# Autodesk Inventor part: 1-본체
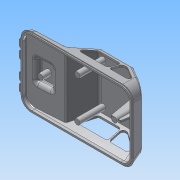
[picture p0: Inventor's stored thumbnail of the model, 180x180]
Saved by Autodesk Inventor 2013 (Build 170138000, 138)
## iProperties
Created: 2015-05
Part Number: 1-본체
Material: ABS 플라스틱
Document SubType Name: Modeling
Designer: Administrator
Density: 1.06 g/cm^3
Mass: 30.7394 g
Surface Area: 295.801 cm^2
Volume: 28.9994 cm^3
Author: Administrator
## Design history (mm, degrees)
sketch "스케치1"
  geometry: L1 (1, -1)-(121, -1); L2 (122, 0)-(118.782, 12.011); L3 (0, 0)-(1.34, 5); L4 (1.34, 5)-(42, 7.131); L5 (56.29, 30)-(92, 30); L6 (92, 30)-(118.782, 12.011); L7 (0, 0)-(1, 0); L8 (1, 0)-(1, -1); L9 (121, -1)-(121, 0); L10 (121, 0)-(122, 0); L11 (42, 7.131)-(56.29, 30); L12 (122, 0)-(122, 10); L13 (118.782, 12.011)-(122, 10); 1 further point
  constraints: 26 end point, 4 perpendicular, 3 parallel, 1 coincident, 1 horizontal
  dimensions: "d1" = 105 deg angle of L1 L2; "d2" = 31 distance between parallel lines of L1 L5; "d9" = 42 horizontal distance of L4.end L3.start; "d10" = 1 distance of L3.start L7.end; "d11" = 1 distance of L7.end L1.start; "d12" = 6 distance from line of L3.end L1; "d14" = 105 deg angle of L3 L1; "d15" = 1 distance of L9.end L2.start; "d16" = 1 distance of L1.end L9.end; "d17" = 30 horizontal distance of L5.end L2.start; "d18" = 122 distance of L2.start L3.start; "d57" = 125 deg angle of L11 L4; "d58" = 3 deg angle of L1 L4; "d137" = 20 distance from line of L12.end L5
extrude "돌출1" new body sketch "스케치1" stored distance "d19" = 76; taper "d20" = 0 deg
node "작업 평면2"
node "작업 평면3"
node "작업 평면4"
node "작업 평면5"
sketch "스케치7"
  geometry: L1 (1, -38)-(0, -38) reference; L2 (0, -38)-(-5, -38) reference; L3 (-5, -38)-(-7.131, -38) reference; L4 (-7.131, -38)-(-7.131, 38) reference; L5 (-30, 38)-(-7.131, 38) reference; L6 (-30, -38)-(-30, 38) reference; L7 (-7.131, -38)-(-30, -38) reference; L8 (1, -38)-(1, 38) reference; L9 (1, -37)-(0, -37); L10 (0, -37)-(0, -38); L11 (0, -38)-(-30, -29.962); L12 (0, 0)-(12, 0); L13 (0, 38)-(-30, 29.962); L14 (0, 37)-(0, 38); L15 (1, 37)-(0, 37); L16 (0, -38)-(1, -38); L17 (1, -37)-(1, -38); L18 (0, -38)-(-30, -38); L19 (-30, -29.962)-(-30, -38); L20 (1, 37)-(1, 38); L21 (1, 38)-(0, 38); L22 (0, 38)-(-30, 38); L23 (-30, 38)-(-30, 29.962)
  constraints: 30 end point, 5 perpendicular, 4 symmetric about line, 3 point on line, 1 collinear
  dimensions: "d84" = 1 distance of L9.end L10.end; "d86" = 1 distance of L9.start L9.end; "d87" = 105 deg angle of L8 L11; "d88" = 105 deg angle of L8 L13
extrude "돌출5" cut sketch "스케치7" stored distance "d89" = 5; taper "d90" = 0 deg
sketch "스케치8"
  geometry: L1 (9.4, 23.66)-(29.4, 23.66); L2 (29.4, 23.66)-(29.4, 49.66); L3 (29.4, 49.66)-(9.4, 49.66); L4 (9.4, 49.66)-(9.4, 23.66); L5 (-1.6, 74.66)-(-1.6, -1.34) reference; 2 further points
  constraints: 8 end point, 2 parallel, 1 horizontal, 1 horizontal alignment, 1 midpoint, 1 perpendicular
  dimensions: "d91" = 26 distance of L1.end L2.end; "d93" = 20 distance of L2.end L3.end; "d94" = 11 distance between parallel lines of L4 L5
extrude "돌출6" join sketch "스케치8" distance "d95" = 5; taper "d96" = -20 deg
fillet "모깎기5" dims "d97" = 3
fillet "모깎기6" dims "d98" = 3
fillet "모깎기7" dims "d99" = 12
feature "쉘1" dims "d42" = 2
node "작업 평면6"
sketch "스케치11"
  geometry: L1 (42, 7.131)-(56.29, 30) reference; L2 (56.29, 30)-(92, 30) reference; L3 (92, 30)-(104.647, 21.505) reference; L4 (104.647, 21.505)-(118.782, 12.011) reference; L5 (49.689, 10)-(59.062, 25); L6 (59.062, 25)-(90.477, 25); L7 (11.591, 0)-(110.409, 0) reference; L8 (109, -1)-(13, -1) reference; L9 (112.808, 10)-(49.689, 10); L10 (83.689, 10)-(83.689, 25); L11 (84.808, 10)-(84.808, 25); L12 (112.808, 10)-(90.477, 25); 1 further point
  constraints: 12 end point, 4 point on line, 3 parallel, 2 perpendicular
  dimensions: "d126" = 5 distance between parallel lines of L1 L5; "d128" = 5 distance between parallel lines of L2 L6; "d129" = 15 distance between parallel lines of L9 L6; "d135" = 34 distance from line of L10 L5.start; "d136" = 28 distance from line of L11 L9.start; "d138" = 5 distance between parallel lines of L3 L12
extrude "돌출8" cut sketch "스케치11" stored distance "d139" = 5; taper "d140" = 0 deg
node "작업 평면7"
sketch "스케치12"
  geometry: L1 (0, 0)-(17.273, 0); A1 r 4 centre (0, -21) between (0, -17) and (0, -25); A2 r 4 centre (0, -10) between (0, -6) and (0, -14); A3 r 4 centre (0, 10) between (0, 14) and (0, 6); A4 r 4 centre (0, 21) between (0, 25) and (0, 17); 2 further points
  constraints: 8 point on circle, 4 centre point, 3 equal radius, 2 end point, 1 horizontal, 13 other
  dimensions: "d142" = 20 distance of A3.centre A2.centre; "d144" = 10 distance from line of L1 A2.centre; "d145" = 11 distance of A2.centre A1.centre; "d146" = 11 distance of A4.centre A3.centre; "d149" = 4 radius of A1
extrude "돌출9" join sketch "스케치12" stored distance "d150" = 5; taper "d151" = 0 deg
chamfer "모따기2" distance "d152" = 1; stored, may be unused: second distance "d153" = 2, angle "d154" = 45 deg
fillet "모깎기8" dims "d155" = 3
fillet "모깎기9" dims "d156" = 3
sketch "스케치13"
  geometry: L1 (65.71, 3.553)-(65.71, 56.37) reference; 3 further points
  constraints: 1 horizontal alignment, 1 midpoint, 1 other
  dimensions: "d157" = 50 distance from line of L1 point (15.71, 29.962)
feature "엠보싱1" sketch "스케치13" dims "d1" = 105 deg, "d2" = 31, "d9" = 42, "d10" = 1, "d11" = 1, "d12" = 6, "d14" = 105 deg, "d15" = 1, "d16" = 1, "d17" = 30, "d18" = 122, "d57" = 125 deg, "d58" = 3 deg, "d137" = 20, "d158" = 0.5, "d159" = 0
node "작업 평면10"
node "작업 평면11"
sketch "스케치17"
  geometry: L1 (109, -10.591)-(109, -63.409) reference; L2 (-39.8, -37)-(133.8, -37) reference; C1 r 3 at (88, -37); C2 r 3 at (48, -15); C3 r 3 at (48, -59); C4 r 3 at (8, -37); 2 further points
  constraints: 4 centre point, 3 equal radius, 2 horizontal alignment, 1 midpoint, 1 point on line, 1 vertical alignment
  dimensions: "d174" = 6 diameter of C1; "d176" = 21 distance of point (109, -37) C1.centre; "d177" = 40 horizontal distance of C1.centre C2.centre; "d178" = 40 horizontal distance of C2.centre C4.centre; "d179" = 44 distance of C3.centre C2.centre; "d180" = 22 vertical distance of C3.centre point (109, -37)
extrude "돌출11" join sketch "스케치17" stored distance "d181" = 5; taper "d182" = 0 deg
fillet "모깎기10" dims "d183" = 3
fillet "모깎기11" dims "d184" = 3
fillet "모깎기13" dims "d186" = 3
sketch "스케치18"
  geometry: L1 (104, 19.53)-(98, 23.561) reference; L2 (98, 0)-(98, 23.561) reference; L3 (107.246, 19.759)-(92.759, 29.49) reference; L4 (117.848, 12.638)-(107.246, 19.759) reference; L5 (107.246, 19.759)-(117.848, 12.638) reference; L6 (92.759, 29.49)-(107.246, 19.759) reference; L7 (104, 0)-(104, 19.53) reference; L8 (96, 2)-(106, 2); L9 (106, 2)-(108.552, 16.473); L10 (92.149, 27.49)-(105.265, 18.681) reference; L11 (105.265, 18.681)-(117.044, 10.769) reference; L12 (96, 2)-(91.419, 27.981); L13 (101, 2)-(101, 35); L14 (11.591, 0)-(110.409, 0) reference; L15 (108.552, 16.473)-(91.419, 27.981); 2 further points
  constraints: 10 end point, 2 midpoint, 2 perpendicular, 2 point on line, 1 collinear, 1 vertical alignment
  dimensions: "d187" = 20 deg angle of L9 L12; "d188" = 10 deg angle of L13 L12; "d189" = 10 distance of L8.end L8.start; "d191" = 2 distance between parallel lines of L14 L8
extrude "돌출12" join sketch "스케치18" stored distance "d192" = 2; taper "d193" = 5 deg
node "솔리드1"
node "투영된 루프3"
node "투영된 루프6"
other parameters: "d32" = 61, "d49" = 0, "d65" = -2, "d83" = 61, "d100" = 0, "d127" = 15, "d141" = -2, "d172" = 0, "d173" = -1
